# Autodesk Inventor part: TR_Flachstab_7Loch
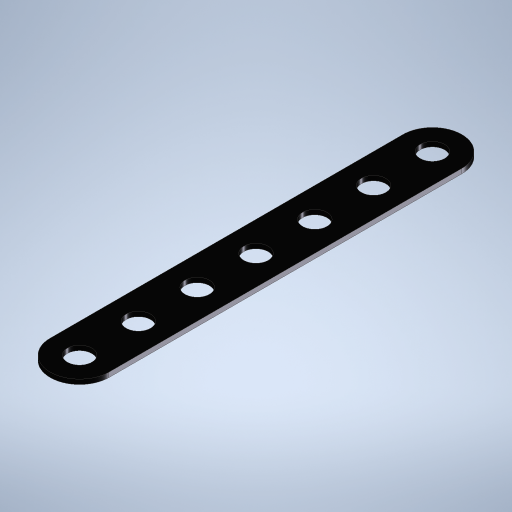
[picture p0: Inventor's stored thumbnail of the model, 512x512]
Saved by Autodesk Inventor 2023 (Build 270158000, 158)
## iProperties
Created: 2023-11
Part Number: TR_Flachstab_7Loch
Material: Edelstahl
Document SubType Name: Modeling
Designer: Admin
Density: 8 g/cm^3
Appearance: Halbpoliert
Author: Admin
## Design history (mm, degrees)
sketch "Skizze1"
  geometry: L1 (0, 30)-(0, -30); L2 (-5, 30)-(-5, -30); L3 (5, -30)-(5, 30); A1 r 5 centre (0, 30) between (5, 30) and (-5, 30); A2 r 5 centre (0, -30) between (-5, -30) and (5, -30); 3 further points
  constraints: 8 end point, 4 point on circle, 4 tangent, 2 centre point, 2 midpoint, 1 horizontal alignment, 1 parallel, 1 vertical, 1 vertical alignment
  dimensions: "d0" = 60 distance of L1.start L1.end (computed from Loch, Einheitsmaß); "d1" = 5 radius of A1 (= 0.5 x Einheitsmaß)
extrude "Extrusion1" new body sketch "Skizze1" distance "d5" = 0.8 (= Dicke); taper "d6" = 0 deg
sketch "Skizze2"
  geometry: C1 r 2.075 at (0, 30); A1 r 5 centre (0, 30) between (5, 30) and (-5, 30) reference; 1 further point
  constraints: 1 centre point, 1 coincident
  dimensions: "d7" = 4.15 diameter of C1 (= 2 x Radius)
extrude "Extrusion2" cut sketch "Skizze2" stored distance "d8" = 10; taper "d9" = 0 deg
pattern_linear "Rechteckige Anordnung1" dims "d12" = 10 (= Einheitsmaß)
node "Volumenkörper1"
other parameters: "Einheitsmaß" = 10 [user parameter; used in 3 equation terms], "Radius" = 2.075 [user parameter; used in 1 equation term], "Fasen" = 0.5 [user parameter], "Dicke" = 0.8 [user parameter; used in 1 equation term]
